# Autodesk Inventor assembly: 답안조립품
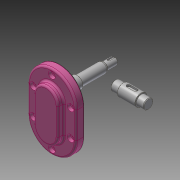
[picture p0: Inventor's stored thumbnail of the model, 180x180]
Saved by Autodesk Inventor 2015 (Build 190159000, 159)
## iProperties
Created: 2020-09
Part Number: 답안조립품
Document SubType Name: Assembly
Designer: LINEART-SSD.D4.16.05
Author: LINEART-SSD.D4.16.05
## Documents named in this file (7)
- C:\Users\LINEART-SSD.D4.16.05\Desktop\700906V1023\답안조립품.iam
- C:\Users\LINEART-SSD.D4.16.05\Desktop\700906V1023\본체.ipt
- C:\Users\LINEART-SSD.D4.16.05\Desktop\700906V1023\커버.ipt
- C:\Users\LINEART-SSD.D4.16.05\Desktop\700906V1023\베어링부시.ipt
- C:\Users\LINEART-SSD.D4.16.05\Desktop\700906V1023\메인축.ipt
- C:\Users\LINEART-SSD.D4.16.05\Desktop\700906V1023\서브축.ipt
- C:\Users\LINEART-SSD.D4.16.05\Desktop\700906V1023\개스킷.ipt
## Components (1 placed, 1 different names)
1. 개스킷:1
